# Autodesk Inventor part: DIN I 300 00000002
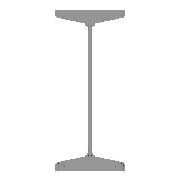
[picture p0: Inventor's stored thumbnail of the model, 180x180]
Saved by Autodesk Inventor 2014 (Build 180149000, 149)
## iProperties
IsCustomPart: 1
Created: 2009-11
Part Number: DIN I 300 00000002
Material: Steel, Mild
Description: Hot rolled I-beam
Document SubType Name: Modeling
Standard: DIN
Designer: pokornp
Standard Revision: 1995
Standards Organization: DIN
Language: en-US
Size Designation: I 300
Categories: <MemberInstance><Categories><Category DisplayName="Structural Shapes" InternalName="089c4875-fa83-4c05-b084-43b9cc11f5ed" Mnemonic="GRDR"><CategoryParameter Dis
Stock Number: I 300
Density: 7.86 g/cm^3
Sheet Metal Rule: Default
Appearance: Steel
_CCFamilyMember: 120
_CCFamilyDisplayName: DIN 1025-1 - Hot rolled I-beam
_FrameMemberDoc: Frame Member File
_Version: 15.0.0
G_L: 10000.000 mm
G_W: 125.000 mm
G_H: 300.000 mm
Author: pokornp
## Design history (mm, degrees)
node "Start plane"
node "End plane"
sketch "Sketch"
  geometry: L1 (5.4, -120.788)-(5.4, 120.788); L2 (-62.5, -150)-(62.5, -150); L3 (-5.4, 120.788)-(-5.4, -120.788); L4 (62.5, 150)-(-62.5, 150); L5 (0, -210)-(0, 210) reference; L6 (-89.185, 0)-(89.185, 0) reference; L7 (-62.5, 150)-(-62.5, 143.828); L8 (-56.901, 137.391)-(-14.703, 131.483); L9 (62.5, 150)-(62.5, 143.828); L10 (56.901, 137.391)-(14.703, 131.483); L11 (-56.901, -137.391)-(-14.703, -131.483); L12 (14.703, -131.483)-(56.901, -137.391); L13 (62.5, -143.828)-(62.5, -150); L14 (-62.5, -150)-(-62.5, -143.828); A1 r 6.5 centre (-56, 143.828) between (-62.5, 143.828) and (-56.901, 137.391); A2 r 6.5 centre (56, 143.828) between (56.901, 137.391) and (62.5, 143.828); A3 r 6.5 centre (56, -143.828) between (62.5, -143.828) and (56.901, -137.391); A4 r 6.5 centre (-56, -143.828) between (-56.901, -137.391) and (-62.5, -143.828); A5 r 10.8 centre (-16.2, 120.788) between (-5.4, 120.788) and (-14.703, 131.483); A6 r 10.8 centre (16.2, 120.788) between (14.703, 131.483) and (5.4, 120.788); A7 r 10.8 centre (16.2, -120.788) between (5.4, -120.788) and (14.703, -131.483); A8 r 10.8 centre (-16.2, -120.788) between (-14.703, -131.483) and (-5.4, -120.788); 6 further points
  constraints: 24 end point, 16 point on circle, 16 tangent, 9 point on line, 8 centre point, 6 equal radius, 4 equal length, 3 parallel, 2 horizontal, 2 vertical, 1 perpendicular, 1 symmetric about line, 3 other
  dimensions: "d3" = 300 vertical distance of L2.end L4.end (= ParH); "d17" = 125 distance of L4.start L4.end (= b); "d22" = 10.8 distance between parallel lines of L3 L1 (= t1); "d28" = 150 distance between parallel lines of L2 L6 (= 0.5 x d3); "d31" = 7.96961 deg angle of L4 L8; "d32" = 31.25 distance from line of point (31.25, -133.8) L13 (= 0.25 x b); "d33" = 16.2 distance from line of L2 point (31.25, -133.8) (= t2); "d34" = 6.5 radius of A1 (= R1); "d35" = 10.8 radius of A5 (= R)
extrude "Body" new body sketch "Sketch" stored distance "d18" = 10000 (= G_L); taper "d19" = 0 deg
node "Driven Length"
  sketch "Sketch3"
    geometry: L1 (0, 0)-(10, 0) reference
    constraints: 2 end point, 1 horizontal
  workplane "Work Plane7"
  sketch "Sketch4"
    geometry: L1 (-2, 0)-(12, 0) reference; L2 (-2, 10000)-(12, 10000) reference
    dimensions: "d37" = 10000 distance between parallel lines of L1 L2 (derived)
body "Solid1"
other parameters: "b" = 125 [user parameter; used in 4 equation terms], "ParH" = 300 [user parameter; used in 1 equation term], "R1" = 6.5 [user parameter; used in 1 equation term], "t1" = 10.8 [user parameter; used in 2 equation terms], "t2" = 16.2 [user parameter; used in 1 equation term], "msp_pom" = 51.7 (= 0.5 x b - t1) [user parameter; used in 1 equation term], "msp_x1" = 3.619 (= 0.07 x msp_pom) [user parameter], "msp_x2" = 4.375 (= 0.035 x b) [user parameter], "G_L" = 10000 (= d37) [user parameter; used in 1 equation term], "R" = 10.8 [user parameter; used in 1 equation term], "d4" = 4.25 (derived), "d6" = 7.47 (derived), "d8" = 0 (derived), "d10" = 0 (derived), "d12" = 4.25 (derived), "d14" = 4.25 (derived), "G_OFFSET_START" = 0 [user parameter; used in 1 equation term], "G_OFFSET_END" = 0 [user parameter; used in 1 equation term], "d29" = 0 (computed from G_OFFSET_START), "Thickness" = 0.5, "BendRadius" = 0.5 (= Thickness), "BendReliefWidth" = 0.5 (= Thickness), "BendReliefDepth" = 0.25 (= 0.5 x Thickness), "CornerReliefSize" = 2 (= 4 x Thickness), "SeamGap" = 0.01, "MinimumRemnant" = 1 (= 2 x Thickness), "TransitionRadius" = 0.5 (= BendRadius), "JacobiRadiusSize" = 0.5 (= Thickness), "d36" = 90 deg, "GapSize" = 0.5 (= Thickness)
